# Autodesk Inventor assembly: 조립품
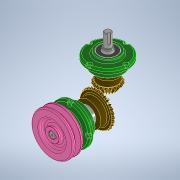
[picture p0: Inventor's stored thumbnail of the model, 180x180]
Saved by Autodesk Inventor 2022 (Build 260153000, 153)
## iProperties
Created: 2023-04
Part Number: 조립품
Document SubType Name: Assembly
Designer: Admin
Author: Admin
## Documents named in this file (14)
- C:\Users\Admin\Desktop\730411V1010\조립품.iam
- C:\Users\Admin\Desktop\730411V1010\본체.ipt
- C:\Users\Admin\Desktop\730411V1010\커버.ipt
- C:\Users\Admin\Desktop\730411V1010\베어링 6203.ipt
- C:\Users\Admin\Desktop\730411V1010\오일실 17 x 32 x 8.ipt
- C:\Users\Admin\Desktop\730411V1010\메인 축.ipt
- 메인 축.ipt
- C:\Users\Admin\Desktop\730411V1010\키 5 x 5 x 14.ipt
- C:\Users\Admin\Desktop\730411V1010\키 4 x 4 x 14.ipt
- C:\Users\Admin\Desktop\730411V1010\메인 베벨기어.ipt
- C:\Users\Admin\Desktop\730411V1010\서브 축.ipt
- 서브 축.ipt
- C:\Users\Admin\Desktop\730411V1010\서브 베벨기어.ipt
- C:\Users\Admin\Desktop\730411V1010\V-벨트풀리.ipt
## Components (1 placed, 1 different names)
1. V-벨트풀리:1
